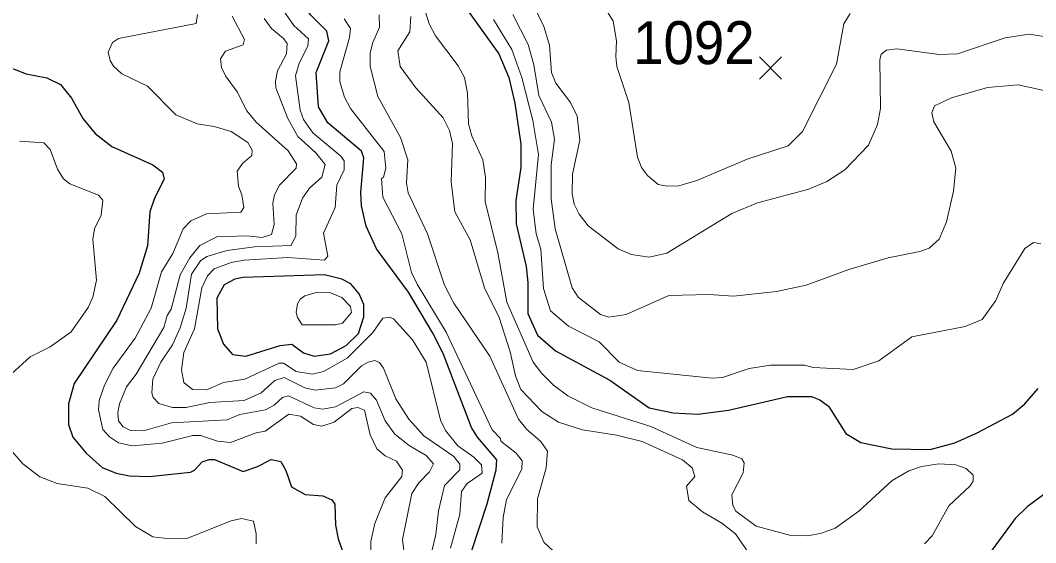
# Model space of a CAD drawing. Extents: x 265 to 291.4, y 7731.5 to 7759.6.
# Drawn here: x 275.364 to 277.255, y 7750.728 to 7751.701 of the extents above; entities that cross this region are included whole.
import ezdxf
from ezdxf.enums import TextEntityAlignment as Align

# ---------------------------------------------------------------- set-up
doc = ezdxf.new("R2010")
doc.units = 0
doc.header["$LTSCALE"] = 0.032
for name, color, linetype, lineweight in [('1', 7, 'Continuous', 25), ('2', 7, 'Continuous', 13), ('21', 7, 'Continuous', 25), ('61', 7, 'Continuous', 13)]:
    doc.layers.add(name, color=color, linetype=linetype, lineweight=lineweight)

msp = doc.modelspace()

# ---------------------------------------------------------------- linework, layer by layer
at = {"layer": '1'}
for points in [[(276.2043, 7750.7113), (276.2337, 7750.8004), (276.2504, 7750.864), (276.252, 7750.8823), (276.2154, 7750.9245), (276.2043, 7750.9427), (276.1518, 7751.0804), (276.1327, 7751.1186), (276.0873, 7751.1949), (276.0277, 7751.2753), (276.0086, 7751.3174), (275.9998, 7751.3556), (275.9982, 7751.3811), (276.0038, 7751.4447), (275.9998, 7751.4574), (275.937, 7751.5099), (275.9195, 7751.5402), (275.9155, 7751.6038), (275.9386, 7751.6627), (275.9354, 7751.681), (275.9044, 7751.7112), (275.8893, 7751.7375), (275.8853, 7751.7772)], [(276.1653, 7751.7645), (276.2552, 7751.6388), (276.2743, 7751.5943), (276.2854, 7751.5465), (276.2965, 7751.4702), (276.2965, 7751.4272), (276.287, 7751.3652), (276.2878, 7751.3222), (276.3061, 7751.2427), (276.3093, 7751.2124), (276.3093, 7751.1552), (276.3276, 7751.1146), (276.361, 7751.0851), (276.462, 7751.031), (276.5352, 7750.9793), (276.5798, 7750.9698), (276.6259, 7750.9674), (276.6832, 7750.9746), (276.793, 7751), (276.8375, 7751), (276.8534, 7750.9944), (276.8693, 7750.9825), (276.9019, 7750.9316), (276.9298, 7750.9149), (276.9871, 7750.903), (277.0586, 7750.9014), (277.1048, 7750.9141), (277.1462, 7750.9324), (277.2122, 7750.9674), (277.2352, 7750.9865), (277.2599, 7751.0152)], [(275.3253, 7751.6205), (275.3754, 7751.6014), (275.4136, 7751.5942), (275.439, 7751.5815), (275.4597, 7751.5561), (275.4804, 7751.5179), (275.5034, 7751.4901), (275.5345, 7751.4662), (275.6109, 7751.432), (275.6291, 7751.4185), (275.6323, 7751.4049), (275.614, 7751.3699), (275.6053, 7751.3445), (275.6013, 7751.2808), (275.5854, 7751.2299), (275.544, 7751.1424), (275.4645, 7751.0247), (275.4541, 7750.9865), (275.4541, 7750.9483), (275.4621, 7750.9245), (275.4867, 7750.895), (275.517, 7750.868), (275.5425, 7750.8576), (275.5679, 7750.8528), (275.6045, 7750.8513), (275.6809, 7750.8592), (275.6888, 7750.8632), (275.7031, 7750.8783), (275.7159, 7750.8831), (275.7262, 7750.8831), (275.7795, 7750.8608), (275.805, 7750.8695), (275.8312, 7750.8831), (275.8495, 7750.8791), (275.859, 7750.8624), (275.8694, 7750.8322), (275.8949, 7750.8178), (275.9275, 7750.8155), (275.9442, 7750.8075), (275.9497, 7750.7996), (275.9513, 7750.7606), (275.9561, 7750.7351), (275.9744, 7750.6842)], [(277.3037, 7750.8425), (277.2392, 7750.7948), (277.2169, 7750.7733), (277.1429, 7750.6723)]]:
    msp.add_lwpolyline(points, dxfattribs=at)
msp.add_lwpolyline([(275.7795, 7751.222), (275.7636, 7751.2188), (275.7437, 7751.2084), (275.7302, 7751.1838), (275.7318, 7751.1265), (275.7429, 7751.0979), (275.7596, 7751.0788), (275.7842, 7751.0756), (275.8479, 7751.0955), (275.8702, 7751.0978), (275.8917, 7751.0819), (275.9116, 7751.0756), (275.9418, 7751.0796), (275.9712, 7751.0955), (275.9943, 7751.1178), (276.0038, 7751.1488), (276.0038, 7751.1718), (275.9951, 7751.1917), (275.98, 7751.21), (275.9633, 7751.2188), (275.9307, 7751.2267)], close=True, dxfattribs=at)
at = {"layer": '2'}
for points in [[(276.0953, 7751.7931), (276.1255, 7751.6945), (276.1375, 7751.6722), (276.1796, 7751.6165), (276.1916, 7751.5943), (276.1971, 7751.5656), (276.1987, 7751.5084), (276.2051, 7751.4861), (276.2258, 7751.4415), (276.2305, 7751.4081), (276.2297, 7751.3636), (276.2536, 7751.2681), (276.2703, 7751.1758), (276.3196, 7751.0645), (276.3355, 7751.043), (276.357, 7751.0215), (276.3841, 7751.0016), (276.4286, 7750.9793), (276.5384, 7750.9443), (276.6243, 7750.9054), (276.6911, 7750.891), (276.7078, 7750.8839), (276.7126, 7750.8767), (276.7102, 7750.8584), (276.6895, 7750.8171), (276.6911, 7750.7972), (276.6967, 7750.7868), (276.7349, 7750.759), (276.7993, 7750.7415), (276.8311, 7750.7407), (276.8566, 7750.7455), (276.8821, 7750.755), (276.9258, 7750.7868), (276.9878, 7750.8441), (277.0189, 7750.8616), (277.0427, 7750.8696), (277.0746, 7750.8751), (277.1064, 7750.8727), (277.1255, 7750.8664), (277.139, 7750.8537), (277.139, 7750.8425), (277.1334, 7750.8338), (277.0936, 7750.7964), (277.0626, 7750.7407), (277.0483, 7750.7256)], [(275.8495, 7751.7263), (275.8734, 7751.6913), (275.9012, 7751.6666), (275.8996, 7751.6531), (275.8837, 7751.6213), (275.8765, 7751.5974), (275.8853, 7751.5338), (275.8917, 7751.5163), (275.9092, 7751.4916), (275.9609, 7751.4479), (275.9672, 7751.4391), (275.9672, 7751.4224), (275.9537, 7751.3938), (275.9505, 7751.3524), (275.9291, 7751.3047), (275.937, 7751.2617), (275.9307, 7751.2546), (275.8622, 7751.2594), (275.7811, 7751.2546), (275.7572, 7751.2498), (275.7254, 7751.2379), (275.7127, 7751.2252), (275.7023, 7751.2029), (275.6888, 7751.1265), (275.6689, 7751.082), (275.6642, 7751.0502), (275.6689, 7751.0263), (275.6848, 7751.0136), (275.7111, 7751.0128), (275.7429, 7751.0263), (275.7827, 7751.0326), (275.8463, 7751.0621), (275.8543, 7751.0621), (275.8781, 7751.047), (275.9084, 7751.0422), (275.9291, 7751.047), (275.9728, 7751.0716), (276.0205, 7751.1193), (276.0396, 7751.1464), (276.0516, 7751.148), (276.0595, 7751.1448), (276.0945, 7751.1058)], [(276.4216, 7751.3185), (276.4048, 7751.3397), (276.396, 7751.3588), (276.392, 7751.3779), (276.3928, 7751.4145), (276.4063, 7751.4781), (276.4016, 7751.5227), (276.3888, 7751.5481), (276.3618, 7751.5839), (276.3538, 7751.6038), (276.3499, 7751.6547), (276.3395, 7751.6897), (276.3204, 7751.7279)], [(276.5324, 7751.4121), (276.5209, 7751.4272), (276.5137, 7751.4463), (276.4978, 7751.5481), (276.4755, 7751.6149), (276.4732, 7751.634), (276.4748, 7751.6627), (276.4684, 7751.6993), (276.4493, 7751.7303)], [(276.0173, 7750.7097), (276.0173, 7750.7304), (276.0245, 7750.7638), (276.0436, 7750.8115), (276.0746, 7750.8513), (276.0762, 7750.8632), (276.0651, 7750.8799), (276.0436, 7750.8895), (276.0285, 7750.903), (276.0158, 7750.9292), (276.0054, 7750.9746), (275.9927, 7750.9801), (275.9816, 7750.9778), (275.9489, 7750.9523), (275.9259, 7750.9451), (275.91, 7750.9483), (275.8861, 7750.9634), (275.8646, 7750.9674), (275.8201, 7750.9356), (275.8034, 7750.9324), (275.7556, 7750.9149), (275.7318, 7750.9173), (275.7, 7750.9276), (275.6856, 7750.9276), (275.6284, 7750.9133), (275.5727, 7750.9085), (275.5472, 7750.9141), (275.5305, 7750.9252), (275.5178, 7750.9388), (275.5098, 7750.9754), (275.5114, 7750.9929), (275.521, 7751.0215), (275.5369, 7751.0533), (275.5782, 7751.109), (275.6077, 7751.1647), (275.6275, 7751.2323), (275.6482, 7751.2665), (275.6673, 7751.3127), (275.6817, 7751.3278), (275.7111, 7751.3405), (275.7747, 7751.3437), (275.7803, 7751.3524), (275.7771, 7751.3763), (275.7707, 7751.3922), (275.7684, 7751.42), (275.7779, 7751.4344), (275.7954, 7751.4495), (275.7962, 7751.459), (275.7882, 7751.4733), (275.7572, 7751.494), (275.7254, 7751.5036), (275.6936, 7751.5083), (275.6538, 7751.525), (275.6013, 7751.5783), (275.5536, 7751.6014), (275.5377, 7751.6157), (275.5313, 7751.6261), (275.5281, 7751.642), (275.5361, 7751.6595), (275.5472, 7751.6674), (275.692, 7751.6953), (275.6944, 7751.712)], [(275.7588, 7751.7088), (275.7819, 7751.6651), (275.7795, 7751.6555), (275.7461, 7751.6436), (275.7373, 7751.6293), (275.7389, 7751.6134), (275.7461, 7751.5974), (275.7684, 7751.568), (275.7859, 7751.5322), (275.8034, 7751.5115), (275.863, 7751.4582), (275.8789, 7751.4336), (275.8781, 7751.4256), (275.8471, 7751.3938), (275.8376, 7751.3763), (275.8344, 7751.3604), (275.8368, 7751.3206), (275.832, 7751.3023), (275.8145, 7751.2967), (275.7859, 7751.2999), (275.7302, 7751.2975), (275.6984, 7751.2816), (275.6801, 7751.2586), (275.6618, 7751.2268), (275.6451, 7751.1631), (275.6379, 7751.1512), (275.6315, 7751.1289), (275.5798, 7751.0422), (275.5623, 7751.0183), (275.5488, 7750.9865), (275.5456, 7750.9706), (275.5472, 7750.9547), (275.556, 7750.9435), (275.5695, 7750.9372), (275.5934, 7750.9364), (275.6459, 7750.9515), (275.7493, 7750.9571), (275.7731, 7750.9666), (275.8209, 7750.9754), (275.8368, 7750.9841), (275.8527, 7750.9984), (275.8638, 7751.0016), (275.9116, 7750.9793), (275.9275, 7750.977), (275.9513, 7750.9809), (276.0038, 7751.0088), (276.0166, 7751.0064), (276.0277, 7750.9937), (276.0436, 7750.9547), (276.0619, 7750.93), (276.0882, 7750.9093), (276.12, 7750.8902), (276.1335, 7750.8751), (276.1263, 7750.86), (276.1064, 7750.8393), (276.0937, 7750.8195), (276.0762, 7750.7336), (276.0881, 7750.6381)], [(276.1247, 7750.6858), (276.1383, 7750.7431), (276.143, 7750.7876), (276.1542, 7750.8346), (276.1828, 7750.864), (276.1828, 7750.8743), (276.1717, 7750.8886), (276.116, 7750.9268), (276.0881, 7750.9579), (276.0635, 7750.9961), (276.0404, 7751.0533), (276.0333, 7751.0637), (276.0245, 7751.0676), (276.0118, 7751.0645), (275.9999, 7751.0573), (275.9664, 7751.0239), (275.9513, 7751.0167), (275.9132, 7751.012), (275.8941, 7751.0167), (275.8559, 7751.0358), (275.8384, 7751.0303), (275.8129, 7751.0072), (275.7811, 7750.9929), (275.7175, 7750.9889), (275.6729, 7750.9801), (275.6475, 7750.9801), (275.622, 7750.9873), (275.6116, 7750.9984), (275.6093, 7751.0072), (275.6109, 7751.0327), (275.626, 7751.0645), (275.6474, 7751.0963), (275.6618, 7751.1281), (275.6729, 7751.1647), (275.6832, 7751.2283), (275.6999, 7751.253), (275.7119, 7751.2609), (275.7493, 7751.2721), (275.8002, 7751.2792), (275.8686, 7751.2816), (275.8773, 7751.2999), (275.8781, 7751.3381), (275.8901, 7751.3699), (275.9028, 7751.3882), (275.9259, 7751.4089), (275.9322, 7751.4328), (275.9147, 7751.4543), (275.8813, 7751.4845), (275.8622, 7751.5179), (275.84, 7751.5752), (275.8392, 7751.5879), (275.8431, 7751.607), (275.8598, 7751.6388), (275.8614, 7751.6579), (275.8543, 7751.6674), (275.832, 7751.6857), (275.8185, 7751.7048)], [(276.2608, 7750.7272), (276.2632, 7750.7749), (276.2695, 7750.8083), (276.2982, 7750.8648), (276.2989, 7750.8807), (276.2878, 7750.895), (276.2592, 7750.9173), (276.2584, 7750.9221), (276.2433, 7750.938), (276.1574, 7751.1202), (276.1033, 7751.2093), (276.0929, 7751.2315), (276.0746, 7751.3031), (276.0396, 7751.3715), (276.0372, 7751.4065), (276.0404, 7751.4089), (276.0452, 7751.4256), (276.042, 7751.4566), (275.9792, 7751.537), (275.968, 7751.5577), (275.9593, 7751.5863), (275.9593, 7751.6054), (275.9776, 7751.669), (275.9792, 7751.6857), (275.9672, 7751.704)], [(276.0325, 7751.7112), (276.0333, 7751.6881), (276.0205, 7751.6595), (276.0158, 7751.6404), (276.0158, 7751.6149), (276.0301, 7751.5593), (276.0722, 7751.4829), (276.0858, 7751.4415), (276.0834, 7751.3986), (276.0866, 7751.3795), (276.1223, 7751.3031), (276.1542, 7751.2077), (276.1717, 7751.1742), (276.2385, 7751.0756), (276.2918, 7750.9579), (276.3077, 7750.9388), (276.3332, 7750.9173), (276.3459, 7750.8982)], [(276.7269, 7750.7001), (276.6959, 7750.7447), (276.6705, 7750.7646), (276.6346, 7750.7853), (276.6092, 7750.8067), (276.6052, 7750.833), (276.6203, 7750.8513), (276.6155, 7750.8672), (276.5973, 7750.8823), (276.5225, 7750.9165), (276.4748, 7750.9284), (276.4111, 7750.938), (276.3666, 7750.9523), (276.3355, 7750.9722), (276.2966, 7751.0136), (276.2862, 7751.039), (276.2767, 7751.0836), (276.256, 7751.1472), (276.2289, 7751.2029), (276.2019, 7751.292), (276.1733, 7751.3445), (276.1669, 7751.4002), (276.1693, 7751.4718), (276.1637, 7751.4956), (276.1518, 7751.5195), (276.1009, 7751.5752), (276.0714, 7751.6149), (276.0675, 7751.6444), (276.0897, 7751.6794), (276.0913, 7751.708)], [(277.2647, 7751.2848), (277.2512, 7751.2872), (277.2352, 7751.2761), (277.1947, 7751.2108), (277.1811, 7751.179), (277.1557, 7751.144), (277.1239, 7751.1305), (277.0244, 7751.1114), (276.9632, 7751.0668), (276.9155, 7751.0509), (276.8407, 7751.0541), (276.8248, 7751.0589), (276.7611, 7751.0589), (276.7214, 7751.0525), (276.672, 7751.0358), (276.653, 7751.0342), (276.5137, 7751.0486), (276.4795, 7751.0645), (276.4421, 7751.1019), (276.3849, 7751.1313), (276.3515, 7751.1599), (276.3387, 7751.2013), (276.3339, 7751.2745), (276.3252, 7751.3031), (276.3196, 7751.3493), (276.3292, 7751.4511), (276.3188, 7751.5147), (276.2981, 7751.5943), (276.2799, 7751.6468), (276.2456, 7751.7025)], [(276.3602, 7751.3127), (276.353, 7751.3683), (276.353, 7751.432), (276.3594, 7751.4797), (276.3538, 7751.5115), (276.33, 7751.5609), (276.3204, 7751.6181), (276.3101, 7751.6563), (276.2814, 7751.712)], [(276.9099, 7751.7136), (276.8979, 7751.6945), (276.8844, 7751.6197), (276.8208, 7751.494), (276.7945, 7751.467), (276.7182, 7751.4423)], [(277.3387, 7751.6603), (277.2432, 7751.6754), (277.1987, 7751.6682), (277.1096, 7751.6388), (277.0761, 7751.6372), (276.9966, 7751.6483), (276.9775, 7751.6452)], [(276.9775, 7751.6452), (276.9672, 7751.638), (276.9648, 7751.6277), (276.9664, 7751.537), (276.9608, 7751.5068), (276.9441, 7751.4686), (276.8996, 7751.4224), (276.8661, 7751.4009), (276.8327, 7751.3866), (276.7373, 7751.3612), (276.6895, 7751.3413), (276.5686, 7751.2673), (276.5352, 7751.2601), (276.5018, 7751.2649), (276.4779, 7751.2753), (276.4216, 7751.3185)], [(277.2734, 7751.5696), (277.2225, 7751.5807), (277.1652, 7751.576), (277.0984, 7751.5569), (277.0666, 7751.5417), (277.0618, 7751.529), (277.0658, 7751.5123), (277.0976, 7751.4574), (277.1064, 7751.4256), (277.1024, 7751.3827), (277.0889, 7751.3254), (277.0753, 7751.2936), (277.0571, 7751.2769), (277.0395, 7751.2705), (276.9807, 7751.2586), (276.9075, 7751.2371), (276.828, 7751.2076), (276.7723, 7751.1957), (276.6927, 7751.187), (276.6466, 7751.1901), (276.5718, 7751.1885), (276.4923, 7751.1528), (276.4604, 7751.148), (276.4445, 7751.1528), (276.4032, 7751.1854), (276.392, 7751.2029), (276.3602, 7751.3127)], [(275.3475, 7751.0422), (275.3826, 7751.074), (275.42, 7751.0931), (275.4589, 7751.1209), (275.4907, 7751.1663), (275.4995, 7751.1854), (275.5059, 7751.2172), (275.4995, 7751.2936), (275.5027, 7751.3127), (275.5146, 7751.3381), (275.5178, 7751.366), (275.5098, 7751.3755), (275.4565, 7751.3962), (275.4446, 7751.4057), (275.4335, 7751.424), (275.4199, 7751.4606), (275.408, 7751.4726), (275.3627, 7751.4757)], [(276.7182, 7751.4423), (276.6243, 7751.4025), (276.5909, 7751.393), (276.5686, 7751.3922), (276.5519, 7751.3954), (276.5324, 7751.4121)], [(276.0945, 7751.1058), (276.12, 7751.0645), (276.147, 7750.9563), (276.1558, 7750.9372), (276.1788, 7750.9086), (276.2091, 7750.8871), (276.2234, 7750.8727)], [(275.579, 7750.7582), (275.5218, 7750.8139), (275.49, 7750.8298), (275.4327, 7750.8385), (275.4009, 7750.8505), (275.369, 7750.8751), (275.3483, 7750.8982)], [(276.3459, 7750.8982), (276.3435, 7750.8672), (276.3276, 7750.8099), (276.3268, 7750.7574), (276.3395, 7750.7288), (276.357, 7750.7121), (276.3745, 7750.7009)], [(276.2234, 7750.8727), (276.2242, 7750.8576), (276.1963, 7750.8385), (276.186, 7750.8234), (276.1828, 7750.7813), (276.1653, 7750.7176)], [(275.7986, 7750.7678), (275.7763, 7750.7733), (275.7572, 7750.7685), (275.6745, 7750.7359), (275.6427, 7750.7351), (275.6109, 7750.7391), (275.579, 7750.7582)], [(275.8034, 7750.7256), (275.8034, 7750.7447), (275.7986, 7750.7678)]]:
    msp.add_lwpolyline(points, dxfattribs=at)
msp.add_lwpolyline([(275.9421, 7751.1933), (275.9633, 7751.1846), (275.9792, 7751.1679), (275.9808, 7751.1567), (275.9641, 7751.1368), (275.9513, 7751.1337), (275.8893, 7751.1337), (275.8805, 7751.1472), (275.8781, 7751.1567), (275.8805, 7751.1727), (275.8853, 7751.1814), (275.8941, 7751.1878), (275.9179, 7751.1949)], close=True, dxfattribs=at)
at = {"layer": '21'}
for p, q in [((276.7407, 7751.6329), (276.7819, 7751.5917)), ((276.7819, 7751.6329), (276.7407, 7751.5917))]:
    msp.add_line(p, q, dxfattribs=at)

# ---------------------------------------------------------------- texts
at = {"layer": '61', "width": 0.95}
msp.add_text('1092', height=0.08, dxfattribs=at).set_placement((276.6187, 7751.6195), align=Align.CENTER)

doc.saveas('drawing.dxf')
